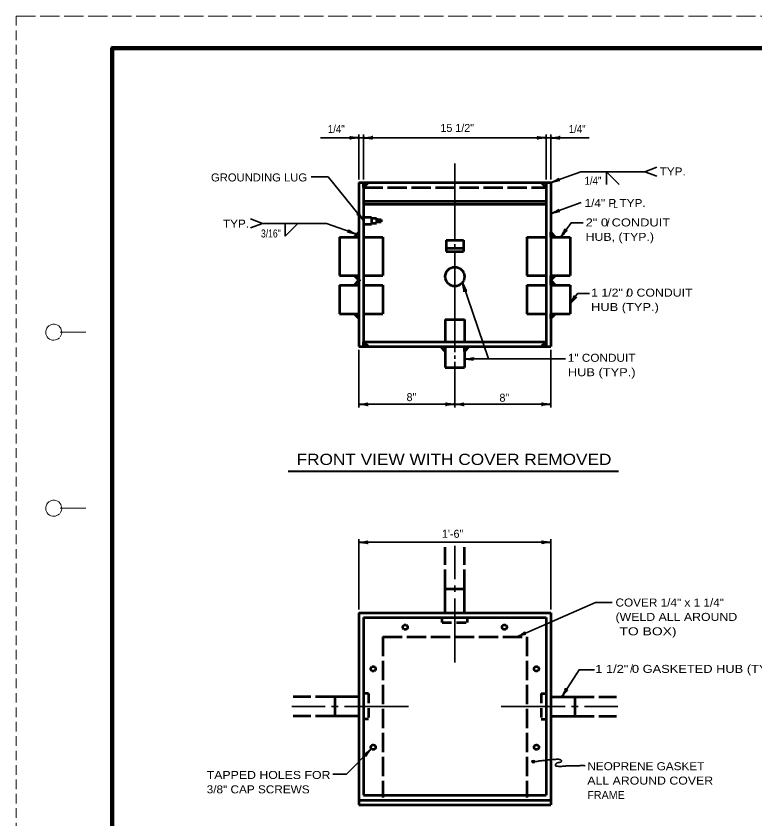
# Model space of a CAD drawing. Extents: x -1 to 679, y 0 to 440.
# Drawn here: x -1.3 to 229.6, y 189.6 to 440.4 of the extents above; entities that cross this region are included whole.
import ezdxf

# ---------------------------------------------------------------- set-up
doc = ezdxf.new("R2010")
doc.units = 0
doc.header["$PDMODE"] = 32
doc.header["$PDSIZE"] = 0.5
doc.linetypes.add('LONG_DASHED', pattern=[7.5, 6, -1.5])
doc.linetypes.add('MEDIUM_DASHED', pattern=[4.5, 3, -1.5])
doc.layers.add('1', color=7, linetype='Continuous', lineweight=53)
doc.layers.add('61', color=7, linetype='Continuous', lineweight=35)

msp = doc.modelspace()

# ---------------------------------------------------------------- hatches: boundary and pattern name
at = {"layer": '1'}
msp.add_hatch(color=256, dxfattribs=at).paths.add_polyline_path([(160.802, 207.473, 1), (159.802, 207.473, 1)])

# ---------------------------------------------------------------- linework, layer by layer
at = {"layer": '1', "linetype": 'MEDIUM_DASHED', "lineweight": 13}
msp.add_line((-1.237, 440.398), (-1.297, 0.358), dxfattribs=at)
at = {"layer": '1', "lineweight": 35}
for p, q in [((105.803, 402.364), (93.803, 402.364)), ((105.803, 389.364), (105.803, 403.364)), ((105.803, 402.364), (107.303, 402.364)), ((107.303, 389.364), (107.303, 403.364)), ((107.303, 402.364), (164.303, 402.364)), ((164.303, 389.364), (164.303, 403.364)), ((164.303, 402.364), (165.803, 402.364)), ((165.803, 389.364), (165.803, 403.364)), ((165.803, 402.364), (177.803, 402.364)), ((135.803, 394.364), (135.803, 370.114)), ((183.2, 391.784), (183.2, 387.784)), ((183.2, 391.784), (187.2, 387.784)), ((195.2, 391.784), (198.959, 390.416)), ((165.803, 378.681), (175.282, 382.131)), ((75.743, 375.642), (71.984, 377.011)), ((75.743, 375.642), (71.984, 374.274)), ((95.743, 375.642), (75.743, 375.642)), ((82.743, 371.642), (82.743, 375.642)), ((82.743, 371.642), (86.743, 375.642)), ((105.14, 372.222), (95.743, 375.642)), ((135.803, 369.114), (135.803, 368.114)), ((135.803, 367.114), (135.803, 366.864)), ((171.827, 350.487), (174.169, 353.674)), ((174.169, 353.674), (177.909, 353.674)), ((105.803, 336.114), (105.803, 318.114)), ((165.803, 336.114), (165.803, 318.114)), ((135.803, 334.364), (135.803, 333.364)), ((135.803, 332.364), (135.803, 318.114)), ((146.272, 333.267), (170.383, 333.267)), ((105.803, 254.972), (105.803, 276.989)), ((105.803, 275.989), (165.803, 275.989)), ((165.803, 254.972), (165.803, 276.989)), ((135.803, 264.472), (135.803, 274.913)), ((135.803, 260.472), (135.803, 262.472)), ((135.803, 258.472), (135.803, 238.472)), ((95.303, 224.722), (84.863, 224.722)), ((99.303, 224.722), (97.303, 224.722)), ((101.303, 224.722), (121.303, 224.722)), ((150.303, 224.722), (170.303, 224.722)), ((172.303, 224.722), (174.303, 224.722)), ((176.303, 224.722), (186.743, 224.722))]:
    msp.add_line(p, q, dxfattribs=at)
at = {"layer": '1'}
for p, q in [((105.803, 388.364), (165.803, 388.364)), ((105.803, 388.364), (105.803, 371.364)), ((107.303, 388.364), (107.303, 375.364)), ((164.303, 388.364), (164.303, 337.114)), ((107.303, 382.614), (164.303, 382.614)), ((107.303, 381.614), (164.303, 381.614)), ((107.303, 377.614), (109.803, 377.614)), ((109.803, 377.614), (109.803, 375.364)), ((109.803, 377.239), (111.303, 377.239)), ((111.303, 377.239), (111.303, 375.739)), ((111.303, 376.864), (112.803, 376.864)), ((112.803, 376.864), (112.803, 376.114)), ((107.303, 375.364), (109.803, 375.364)), ((107.303, 375.364), (107.303, 337.114)), ((109.803, 375.739), (111.303, 375.739)), ((111.303, 376.114), (112.803, 376.114)), ((99.803, 371.364), (99.803, 359.364)), ((99.803, 371.364), (105.803, 371.364)), ((105.803, 371.364), (105.803, 357.864)), ((107.303, 371.364), (113.303, 371.364)), ((113.303, 371.364), (113.303, 359.364)), ((158.303, 371.364), (158.303, 359.364)), ((158.303, 371.364), (164.303, 371.364)), ((165.803, 371.364), (171.803, 371.364)), ((171.803, 371.364), (171.803, 359.364)), ((133.053, 370.364), (138.553, 370.364)), ((133.053, 370.364), (133.053, 366.864)), ((138.553, 370.364), (138.553, 366.864)), ((133.053, 367.864), (138.553, 367.864)), ((133.053, 366.864), (138.553, 366.864)), ((99.803, 359.364), (105.803, 359.364)), ((107.303, 359.364), (113.303, 359.364)), ((158.303, 359.364), (164.303, 359.364)), ((165.803, 359.364), (171.803, 359.364)), ((165.803, 359.364), (165.803, 357.864)), ((99.803, 356.364), (105.803, 356.364)), ((99.803, 356.364), (99.803, 347.364)), ((107.303, 356.364), (113.303, 356.364)), ((113.303, 356.364), (113.303, 347.364)), ((158.303, 356.364), (158.303, 347.364)), ((158.303, 356.364), (164.303, 356.364)), ((165.803, 356.364), (171.803, 356.364)), ((165.803, 356.364), (165.803, 347.364)), ((171.803, 356.364), (171.803, 347.364)), ((99.803, 347.364), (105.803, 347.364)), ((107.303, 347.364), (113.303, 347.364)), ((158.303, 347.364), (164.303, 347.364)), ((165.803, 347.364), (171.803, 347.364)), ((165.803, 347.364), (165.803, 337.114)), ((132.803, 345.614), (138.803, 345.614)), ((132.803, 345.614), (132.803, 338.614)), ((138.803, 345.614), (138.803, 338.614)), ((107.303, 338.614), (164.303, 338.614)), ((132.803, 337.114), (132.803, 330.614)), ((138.803, 337.114), (138.803, 330.614)), ((132.803, 330.614), (138.803, 330.614)), ((132.803, 253.972), (132.803, 261.472)), ((132.803, 261.472), (138.803, 261.472)), ((138.803, 253.972), (138.803, 261.472)), ((105.803, 253.972), (165.803, 253.972)), ((105.803, 253.972), (105.803, 193.972)), ((165.803, 253.972), (165.803, 193.972)), ((107.303, 252.472), (164.303, 252.472)), ((107.303, 252.472), (107.303, 196.972)), ((164.303, 252.472), (164.303, 196.972)), ((105.803, 227.722), (98.303, 227.722)), ((98.303, 227.722), (98.303, 221.722)), ((165.803, 227.722), (173.303, 227.722)), ((173.303, 227.722), (173.303, 221.722)), ((105.803, 221.722), (98.303, 221.722)), ((165.803, 221.722), (173.303, 221.722)), ((107.303, 196.972), (164.303, 196.972)), ((105.803, 195.472), (165.803, 195.472)), ((105.803, 193.972), (165.803, 193.972))]:
    msp.add_line(p, q, dxfattribs=at)
at = {"layer": '1', "linetype": 'LONG_DASHED'}
for p, q in [((107.303, 386.864), (164.303, 386.864)), ((132.803, 261.472), (132.803, 274.472)), ((138.803, 261.472), (138.803, 274.472)), ((113.303, 246.472), (113.303, 196.222)), ((113.303, 246.472), (158.303, 246.472)), ((158.303, 246.472), (158.303, 196.222)), ((98.303, 227.722), (85.303, 227.722)), ((173.303, 227.722), (186.303, 227.722)), ((98.303, 221.722), (85.303, 221.722)), ((173.303, 221.722), (186.303, 221.722))]:
    msp.add_line(p, q, dxfattribs=at)
at = {"layer": '1', "lineweight": 40}
msp.add_line((83.706, 298.197), (186.915, 298.197), dxfattribs=at)
at = {"layer": '1', "linetype": 'MEDIUM_DASHED'}
for p, q in [((131.803, 250.972), (131.803, 252.472)), ((131.803, 250.972), (139.803, 250.972)), ((139.803, 250.972), (139.803, 252.472)), ((108.803, 228.722), (107.303, 228.722)), ((108.803, 228.722), (108.803, 220.722)), ((162.803, 228.722), (162.803, 220.722)), ((162.803, 228.722), (164.303, 228.722)), ((108.803, 220.722), (107.303, 220.722)), ((162.803, 220.722), (164.303, 220.722))]:
    msp.add_line(p, q, dxfattribs=at)
at = {"layer": '1', "lineweight": 35}
for points in [[(165.803, 388.364), (175.2, 391.784), (195.2, 391.784), (198.959, 393.152)], [(107.303, 376.514), (96.184, 390.181), (90.907, 390.181)], [(168.911, 371.364), (172.132, 375.748), (175.871, 375.748)], [(135.803, 366.864), (135.803, 345.614), (135.803, 335.364)], [(138.167, 357.14), (146.272, 333.267), (138.803, 333.267)], [(105.803, 319.114), (135.803, 319.114), (165.803, 319.114)], [(155.226, 246.472), (179.711, 257.232), (185.009, 257.232)], [(169.25, 227.722), (174.692, 236.175), (179.432, 236.175)], [(109.744, 211.472), (101.922, 203.592), (97.679, 203.592)]]:
    msp.add_lwpolyline(points, dxfattribs=at)
at = {"layer": '1'}
for points in [[(107.303, 388.364), (108.803, 388.364), (107.303, 386.864)], [(162.803, 388.364), (164.303, 388.364), (164.303, 386.864)], [(104.303, 371.364), (105.803, 372.864), (105.803, 371.364)], [(165.803, 372.864), (167.303, 371.364), (165.803, 371.364)], [(105.803, 357.864), (104.303, 359.364), (105.803, 359.364)], [(165.803, 359.364), (167.303, 359.364), (165.803, 357.864)], [(104.303, 356.364), (105.803, 357.864), (105.803, 356.364)], [(165.803, 357.864), (167.303, 356.364), (165.803, 356.364)], [(104.303, 347.364), (105.803, 347.364), (105.803, 345.864)], [(165.803, 347.364), (167.303, 347.364), (165.803, 345.864)], [(107.303, 337.114), (107.303, 338.614), (108.803, 337.114)], [(107.303, 337.114), (107.303, 338.614), (108.803, 337.114)], [(131.303, 337.114), (132.803, 337.114), (132.803, 335.614)], [(138.803, 337.114), (140.303, 337.114), (138.803, 335.614)], [(162.803, 337.114), (164.303, 338.614), (164.303, 337.114)]]:
    msp.add_lwpolyline(points, close=True, dxfattribs=at)
for points in [[(165.803, 388.364), (165.803, 371.364), (165.803, 356.364)], [(105.803, 357.864), (105.803, 345.864), (105.803, 337.114)], [(105.803, 337.114), (107.303, 337.114), (108.468, 337.114)], [(107.303, 337.114), (132.803, 337.114), (140.303, 337.114)], [(140.303, 337.114), (164.303, 337.114), (165.803, 337.114)]]:
    msp.add_lwpolyline(points, dxfattribs=at)
msp.add_circle((135.813, 358.999), 3, dxfattribs=at)
at = {"layer": '1', "linetype": 'LONG_DASHED'}
for centre in [(120.302, 249.474), (151.301, 249.479), (110.303, 236.473), (161.301, 236.472), (110.304, 211.97), (161.306, 211.973)]:
    msp.add_circle(centre, 0.75, dxfattribs=at)
at = {"layer": '1', "lineweight": 13}
msp.add_circle((160.302, 207.473), 0.5, dxfattribs=at)
msp.add_circle((160.302, 207.473), 0.5, dxfattribs=at)
msp.add_circle((160.302, 207.473), 0.5, dxfattribs=at)
at = {"layer": '1', "lineweight": 40}
for centre, major_axis, ratio, start_param, end_param in [((104.712, 402.088), (1.786, 0.156), 0.122415, 0.8963533, 3.1415927), ((104.712, 402.088), (1.786, 0.156), 0.122415, 0.8963533, 3.1415927), ((104.683, 402.575), (1.756, -0.176), 0.07063, 3.1407148, 5.41811), ((104.683, 402.575), (1.756, -0.176), 0.07063, 3.1407148, 5.41811), ((108.394, 402.64), (-1.786, -0.156), 0.122415, 0.8963533, 3.1415927), ((108.394, 402.64), (-1.786, -0.156), 0.122415, 0.8963533, 3.1415927), ((108.424, 402.152), (-1.756, 0.176), 0.07063, 3.1407148, 5.41811), ((108.424, 402.152), (-1.756, 0.176), 0.07063, 3.1407148, 5.41811), ((163.212, 402.088), (1.786, 0.156), 0.122415, 0.8963533, 3.1415927), ((163.212, 402.088), (1.786, 0.156), 0.122415, 0.8963533, 3.1415927), ((163.183, 402.575), (1.756, -0.176), 0.07063, 3.1407148, 5.41811), ((163.183, 402.575), (1.756, -0.176), 0.07063, 3.1407148, 5.41811), ((166.894, 402.64), (-1.786, -0.156), 0.122415, 0.8963533, 3.1415927), ((166.894, 402.64), (-1.786, -0.156), 0.122415, 0.8963533, 3.1415927), ((166.924, 402.152), (-1.756, 0.176), 0.07063, 3.1407148, 5.41811), ((166.924, 402.152), (-1.756, 0.176), 0.07063, 3.1407148, 5.41811), ((166.734, 388.997), (-1.625, -0.757), 0.122415, 0.8963533, 3.1415927), ((166.734, 388.997), (-1.625, -0.757), 0.122415, 0.8963533, 3.1415927), ((166.928, 388.548), (1.711, 0.436), 0.07063, 6.2823074, 8.5597026), ((166.928, 388.548), (1.711, 0.436), 0.07063, 6.2823074, 8.5597026), ((106.76, 377.517), (0.972, -1.473), 0.07063, 3.1407148, 5.41811), ((106.76, 377.517), (0.972, -1.473), 0.07063, 3.1407148, 5.41811), ((166.734, 379.314), (-1.625, -0.757), 0.122415, 0.8963533, 3.1415927), ((166.734, 379.314), (-1.625, -0.757), 0.122415, 0.8963533, 3.1415927), ((166.928, 378.865), (1.711, 0.436), 0.07063, 6.2823074, 8.5597026), ((166.928, 378.865), (1.711, 0.436), 0.07063, 6.2823074, 8.5597026), ((106.4, 377.186), (1.248, -1.287), 0.122415, 0.8963533, 3.1415927), ((106.4, 377.186), (1.248, -1.287), 0.122415, 0.8963533, 3.1415927), ((169.335, 372.407), (-0.931, -1.531), 0.122415, 0.8963533, 3.1415927), ((169.335, 372.407), (-0.931, -1.531), 0.122415, 0.8963533, 3.1415927), ((104.015, 372.407), (-1.711, 0.436), 0.07063, 4.006668, 6.2840632), ((104.015, 372.407), (-1.711, 0.436), 0.07063, 4.006668, 6.2840632), ((104.209, 372.855), (1.625, -0.757), 0.122415, 3.1415927, 5.386832), ((104.209, 372.855), (1.625, -0.757), 0.122415, 3.1415927, 5.386832), ((169.745, 372.142), (-1.182, -1.311), 0.07063, 3.1407148, 5.41811), ((169.745, 372.142), (-1.182, -1.311), 0.07063, 3.1407148, 5.41811), ((138.327, 356.011), (-0.398, 1.72), 0.07063, 3.1407148, 5.41811), ((138.327, 356.011), (-0.398, 1.72), 0.07063, 3.1407148, 5.41811), ((138.78, 356.196), (-0.722, 1.641), 0.122415, 0.8963533, 3.1415927), ((138.78, 356.196), (-0.722, 1.641), 0.122415, 0.8963533, 3.1415927), ((172.251, 351.53), (-0.931, -1.531), 0.122415, 0.8963533, 3.1415927), ((172.661, 351.264), (-1.182, -1.311), 0.07063, 3.1407148, 5.41811), ((139.894, 333.543), (-1.786, -0.156), 0.122415, 0.8963533, 3.1415927), ((139.924, 333.055), (-1.756, 0.176), 0.07063, 3.1407148, 5.41811), ((106.894, 319.39), (-1.786, -0.156), 0.122415, 0.8963533, 3.1415927), ((106.894, 319.39), (-1.786, -0.156), 0.122415, 0.8963533, 3.1415927), ((106.924, 318.902), (-1.756, 0.176), 0.07063, 3.1407148, 5.41811), ((106.924, 318.902), (-1.756, 0.176), 0.07063, 3.1407148, 5.41811), ((134.712, 318.838), (1.786, 0.156), 0.122415, 0.8963533, 3.1415927), ((134.712, 318.838), (1.786, 0.156), 0.122415, 0.8963533, 3.1415927), ((134.683, 319.325), (1.756, -0.176), 0.07063, 3.1407148, 5.41811), ((134.683, 319.325), (1.756, -0.176), 0.07063, 3.1407148, 5.41811), ((136.894, 319.39), (-1.786, -0.156), 0.122415, 0.8963533, 3.1415927), ((136.894, 319.39), (-1.786, -0.156), 0.122415, 0.8963533, 3.1415927), ((136.924, 318.902), (-1.756, 0.176), 0.07063, 3.1407148, 5.41811), ((136.924, 318.902), (-1.756, 0.176), 0.07063, 3.1407148, 5.41811), ((164.712, 318.838), (1.786, 0.156), 0.122415, 0.8963533, 3.1415927), ((164.712, 318.838), (1.786, 0.156), 0.122415, 0.8963533, 3.1415927), ((164.683, 319.325), (1.756, -0.176), 0.07063, 3.1407148, 5.41811), ((164.683, 319.325), (1.756, -0.176), 0.07063, 3.1407148, 5.41811), ((106.894, 276.265), (-1.786, -0.156), 0.122415, 0.8963533, 3.1415927), ((106.924, 275.777), (-1.756, 0.176), 0.07063, 3.1407148, 5.41811), ((164.712, 275.712), (1.786, 0.156), 0.122415, 0.8963533, 3.1415927), ((164.683, 276.2), (1.756, -0.176), 0.07063, 3.1407148, 5.41811), ((156.114, 247.164), (-1.572, -0.861), 0.122415, 0.8963533, 3.1415927), ((156.114, 247.164), (-1.572, -0.861), 0.122415, 0.8963533, 3.1415927), ((156.337, 246.729), (1.679, 0.546), 0.07063, 6.2823074, 8.5597026), ((156.337, 246.729), (1.679, 0.546), 0.07063, 6.2823074, 8.5597026), ((169.609, 228.789), (-0.835, -1.586), 0.122415, 0.8963533, 3.1415927), ((170.035, 228.55), (1.099, 1.382), 0.07063, 6.2823074, 8.5597026), ((108.805, 210.826), (1.362, 1.123), 0.07063, 3.1407148, 5.41811), ((109.172, 210.503), (1.147, 1.377), 0.122415, 0.8963533, 3.1415927)]:
    msp.add_ellipse(centre, major_axis=major_axis, ratio=ratio, start_param=start_param, end_param=end_param, dxfattribs=at)
at = {"layer": '1', "lineweight": 35}
msp.add_spline([(160.806, 207.504), (161.646, 207.566), (161.864, 207.628), (162.113, 207.69), (162.456, 207.721), (162.798, 207.753), (163.11, 207.784), (163.359, 207.815), (163.546, 207.846), (163.733, 207.846), (163.919, 207.877), (164.2, 207.939), (164.511, 207.971), (164.822, 208.002), (165.134, 208.033), (165.414, 208.064), (165.694, 208.095), (165.912, 208.158), (166.13, 208.158), (166.317, 208.189), (166.597, 208.189), (166.909, 208.189), (167.126, 208.189), (167.376, 208.189), (167.594, 208.22), (167.874, 208.22), (168.154, 208.22), (168.372, 208.189), (168.683, 208.095), (168.932, 208.033), (169.088, 207.877), (169.181, 207.721), (169.15, 207.472), (168.964, 207.317), (168.777, 207.285), (168.559, 207.254), (168.341, 207.223), (168.092, 207.161), (167.905, 207.099), (167.687, 207.036), (167.5, 206.912), (167.313, 206.662), (167.251, 206.382), (167.407, 206.102), (167.718, 206.04), (167.998, 206.008), (168.59, 205.977), (168.839, 205.977), (169.026, 205.977), (169.368, 206.008), (169.586, 206.04), (169.835, 206.071), (170.334, 206.102), (170.925, 206.164), (171.174, 206.164), (171.423, 206.164), (172.015, 206.164), (172.326, 206.164), (172.669, 206.164), (173.261, 206.164), (173.634, 206.164), (174.008, 206.164), (174.599, 206.195), (174.911, 206.226), (175.222, 206.226), (175.534, 206.226), (175.907, 206.226), (176.094, 206.226), (176.281, 206.226), (176.53, 206.195), (176.561, 206.195)], degree=3, dxfattribs=at)
at = {"layer": '1'}
msp.add_point((105.803, 357.864), dxfattribs=at)
at = {"layer": '61', "linetype": 'LONG_DASHED', "lineweight": 13}
msp.add_line((-1.237, 440.398), (678.783, 440.398), dxfattribs=at)
at = {"layer": '61', "lineweight": 13}
for p, q in [((12.483, 341.638), (20.463, 341.658)), ((12.463, 286.638), (20.463, 286.638))]:
    msp.add_line(p, q, dxfattribs=at)
at = {"layer": '61', "lineweight": 158}
msp.add_lwpolyline([(667.803, 430.398), (28.763, 430.398), (28.763, 10.378)], dxfattribs=at)
at = {"layer": '61', "lineweight": 13}
for centre, end in [((10.461, 341.639), 316.23216), ((10.461, 286.639), 315.37577)]:
    msp.add_arc(centre, 2.5, 323.13009, end, dxfattribs=at)

# ---------------------------------------------------------------- texts
at = {"layer": '1'}
for s, height, width, p in [('1/4"', 2.5, 0.9, (96.138, 403.858)), ('1/4"', 2.5, 0.9, (171.41, 403.858)), ('TYP.', 2.5, 1.1, (199.786, 390.601)), ('GROUNDING LUG', 2.5, 1.05, (59.607, 388.731)), ('1/4"', 2.5, 0.9, (176.338, 387.711)), ('1/4" P TYP.', 2.5, 1.1, (176.338, 380.743)), ('L', 2.5, 0.75, (185.343, 380.403)), ('TYP.', 2.5, 1.1, (63.345, 374.284)), ('2" 0 CONDUIT', 2.5, 1.2, (176.678, 374.673)), ('3/16"', 2.5, 0.8, (75.239, 371.224)), ('HUB, (TYP.)', 2.5, 1.15, (176.678, 370.173)), ('1 1/2" 0 CONDUIT', 2.5, 1.15, (178.377, 352.747)), ('HUB (TYP.)', 2.5, 1.2, (178.377, 348.247)), ('1" CONDUIT', 2.5, 1.1, (171.113, 332.387)), ('HUB (TYP.)', 2.5, 1.2, (171.113, 327.887)), ('FRONT VIEW WITH COVER REMOVED', 3.5, 1.15, (86.351, 300.158)), ('COVER 1/4" x 1 1/4"', 2.5, 1.1, (186.01, 255.938)), ('(WELD ALL AROUND', 2.5, 1.15, (186.01, 251.438)), (' TO BOX)', 2.5, 1.3, (186.01, 246.938)), ('1 1/2" 0 GASKETED HUB (TYP.)', 2.5, 1.2, (179.679, 235.199)), ('NEOPRENE GASKET', 2.5, 1.1, (177.198, 204.798)), ('TAPPED HOLES FOR', 2.5, 1.15, (58.274, 202.06)), ('ALL AROUND COVER', 2.5, 1.15, (177.198, 200.298)), ('3/8" CAP SCREWS', 2.5, 1.1, (58.274, 197.56))]:
    msp.add_text(s, height=height, dxfattribs=dict(at, width=width)).set_placement(p)
for s, p in [('15 1/2"', (131.311, 404.198)), ('/', (183.259, 374.598)), ('/', (189.375, 352.681)), ('8"', (120.72, 320.093)), ('8"', (149.751, 319.91)), ('1\'-6"', (131.788, 277.399)), ('/', (190.545, 235.285)), ('FRAME', (177.198, 195.798))]:
    msp.add_text(s, height=2.5, dxfattribs=at).set_placement(p)

doc.saveas('drawing.dxf')
